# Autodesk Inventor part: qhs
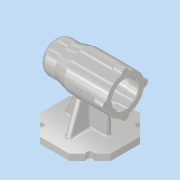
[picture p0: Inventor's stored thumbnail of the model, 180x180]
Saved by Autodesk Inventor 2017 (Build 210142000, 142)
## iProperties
Created: 2019-12
Part Number: qhs
Material: 알루미늄 6061
Document SubType Name: Modeling
Designer: 5-15-le-1
Density: 2.7 g/cm^3
Appearance: 알루미늄 - 짙음
Mass: 725.664 g
Surface Area: 714.987 cm^2
Volume: 268.764 cm^3
Author: 5-15-le-1
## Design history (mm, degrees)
sketch "스케치3" dims "d0" = 112
  geometry: L1 (-56, -23.196)-(-56, 23.196); L2 (-56, 23.196)-(-23.196, 56); L3 (-23.196, 56)-(23.196, 56); L4 (23.196, 56)-(56, 23.196); L5 (56, 23.196)-(56, -23.196); L6 (56, -23.196)-(23.196, -56); L7 (23.196, -56)-(-23.196, -56); L8 (-23.196, -56)-(-56, -23.196); 4 further points
  constraints: 16 end point, 2 coincident, 1 horizontal, 1 midpoint, 20 other
extrude "돌출1" new body sketch "스케치3" distance "d1" = 10; taper "d2" = 0 deg
sketch "스케치4"
  geometry: L1 (56, 23.196)-(23.196, 56) reference; L2 (-23.196, 56)-(-56, 23.196) reference; L3 (23.196, -56)-(56, -23.196) reference; L4 (-23.196, -56)-(-56, -23.196) reference; C1 r 5 at (-39.598, -39.598); C2 r 5 at (-39.598, 39.598); C3 r 5 at (39.598, 39.598); C4 r 5 at (39.598, -39.598); 1 further point
  constraints: 4 centre point, 4 midpoint, 3 equal radius
  dimensions: "d3" = 10 diameter of C1
extrude "돌출2" cut sketch "스케치4" stored distance "d4" = 10; taper "d5" = 0 deg
sketch "스케치5"
  geometry: L1 (56, 110)-(-11, 110); L2 (-11, 110)-(-31, 105); L3 (-31, 105)-(-56, 105); L4 (-56, 80)-(56, 80); L5 (56, 80)-(56, 110); L6 (-56, 105)-(-56, 80); L7 (56, 0)-(43.134, 0) reference; 2 further points
  constraints: 12 end point, 2 horizontal, 1 parallel, 1 perpendicular, 1 vertical, 1 vertical alignment
  dimensions: "d6" = 112 distance between parallel lines of L5 L6; "d7" = 25 distance of L2.end L3.end; "d8" = 45 distance from line of L6 L1.end; "d9" = 50 diameter of L3 L4; "d10" = 60 diameter of L1 L4; "d11" = 80 distance between parallel lines of L7 L4
revolve "회전1" sketch "스케치5" stored, may be unused: angle "d12" = 90 deg
sketch "스케치6"
  geometry: L1 (-14.685, 60)-(-38, 10); L2 (-56, 10)-(-43.134, 10) reference; L3 (-38, 10)-(31, 10); L4 (23.196, 10)-(36.062, 10) reference; L5 (31, 10)-(31, 60); L6 (31, 60)-(-14.685, 60); L7 (-56, 0)-(-56, 10) reference; L8 (56, 0)-(56, 10) reference; L9 (-11, 50)-(-11, 110) reference; L10 (56, 50)-(56, 110) reference; 1 further point
  constraints: 8 end point, 2 point on line, 1 perpendicular, 1 vertical
  dimensions: "d13" = 115 deg angle of L2 L1; "d14" = 18 distance from line of L7 L1.end; "d15" = 25 distance between parallel lines of L8 L5; "d16" = 10 distance from line of L9.start L6
extrude "돌출3" join sketch "스케치6" stored distance "d17" = 8; taper "d18" = 0 deg
sketch "스케치7"
  geometry: L1 (56.766, 18.979)-(10, 36); L2 (10, 36)-(10, -36); L3 (10, -36)-(56.766, -18.979); L4 (10, -36.062)-(10, -23.196) reference; L5 (52.125, 4)-(50.268, 4) reference; L6 (50.268, -4)-(52.125, -4) reference; L7 (0, 56)-(10, 56) reference; L8 (0, -56)-(10, -56) reference; L9 (10, -56)-(10, -43.134) reference; L10 (10, 43.134)-(10, 56) reference; C1 r 25 at (80, 0) reference; A1 r 30 centre (80, 0) between (50.268, -4) and (50.268, 4) reference; 2 further points; 1 other entity
  constraints: 6 end point, 2 point on circle, 1 collinear, 1 other
  dimensions: "d19" = 20 distance from line of L7 L1.end; "d20" = 20 distance from line of L8 L2.end; "d21" = 110 deg angle of L9 L3; "d22" = 110 deg angle of L10 L1
extrude "돌출4" join sketch "스케치7" stored distance "d23" = 8; taper "d24" = 0 deg
sketch "스케치8"
  geometry: L1 (56, 50)-(56, 110) reference; L2 (56, 80)-(-56, 80); L3 (-56, 55)-(-56, 105) reference; L4 (-50, 80)-(-50, 90.5); L5 (-50, 90.5)-(-47, 90.5); L6 (-47, 90.5)-(-47, 96); L7 (-47, 96)-(-43, 96); L8 (-43, 96)-(-43, 97.5); L9 (-25, 97.5)-(-25, 101); L10 (-25, 101)-(-13, 101); L11 (-13, 101)-(-13, 104); L12 (-13, 104)-(41, 104); L13 (41, 104)-(41, 101); L14 (41, 101)-(56, 101); L15 (-43, 97.5)-(-25, 97.5); 1 further point
  constraints: 26 end point, 7 perpendicular, 2 midpoint, 2 point on line, 2 vertical, 1 horizontal, 1 parallel
  dimensions: "d25" = 42 diameter of L14 L2; "d26" = 15 distance of L13.end L14.end; "d27" = 48 diameter of L12 L2; "d28" = 54 distance of L11.end L12.end; "d29" = 12 distance of L9.end L10.end; "d30" = 42 diameter of L10 L2; "d31" = 18 distance of L8.end L9.start; "d32" = 35 diameter of L15 L2; "d33" = 4 distance of L6.end L7.end; "d34" = 3 distance of L4.end L5.end; "d35" = 32 diameter of L7 L2; "d36" = 21 diameter of L5 L2
revolve "회전2" sketch "스케치8" stored, may be unused: angle "d37" = 90 deg
sketch "스케치9"
  geometry: C1 r 6 at (0, 30); 2 further points
  constraints: 1 centre point, 1 vertical alignment, 1 other
  dimensions: "d38" = 12 diameter of C1
extrude "돌출5" join sketch "스케치9" distance "d39" = 16; taper "d40" = 0 deg
hole "구멍1" diameter "d43" = 3.459; stored, may be unused: countersink angle "d47" = 90 deg, drill point angle "d49" = 118 deg; dims "d41" = 10, "d42" = 10, "d44" = 8, "d45" = 4, "d46" = 2, "d48" = 11
fillet "모깎기1" dims "d50" = 3
fillet "모깎기2" dims "d52" = 1
fillet "모깎기3" dims "d56" = 0.3
fillet "모깎기4" dims "d57" = 3
chamfer "모따기1" distance "d58" = 1; stored, may be unused: second distance "d59" = 2, angle "d60" = 45 deg
fillet "모깎기5" dims "d61" = 10
fillet "모깎기6" dims "d62" = 3
fillet "모깎기7" dims "d63" = 3
fillet "모깎기8" dims "d64" = 3
node "작업 평면1"
sketch "스케치10"
  geometry: L1 (-28.5, 3.5)-(13.5, 3.5); L2 (13.5, 3.5)-(13.5, -3.5); L3 (13.5, -3.5)-(-28.5, -3.5); L4 (-28.5, -3.5)-(-28.5, 3.5); L5 (-28.5, 0)-(13.5, 0); L6 (-7.5, 3.5)-(-7.5, -3.5); L7 (33.5, -22)-(33.5, 22) reference; L8 (33.5, 0)-(-78.5, 0); L9 (-78.5, -15)-(-78.5, 15) reference; 1 further point
  constraints: 6 end point, 6 midpoint, 1 collinear, 2 other
  dimensions: "d65" = 42 distance of L1.start L1.end; "d66" = 7 distance of L1.end L2.end; "d67" = 41 distance between parallel lines of L7 L6
feature "엠보싱1" sketch "스케치10" dims "d3" = 10, "d68" = 0.5, "d69" = 0
node "솔리드1"
pattern_circular "원형 패턴1" dims "d54" = 360 deg
node "투영된 루프1"
node "투영된 루프2"
